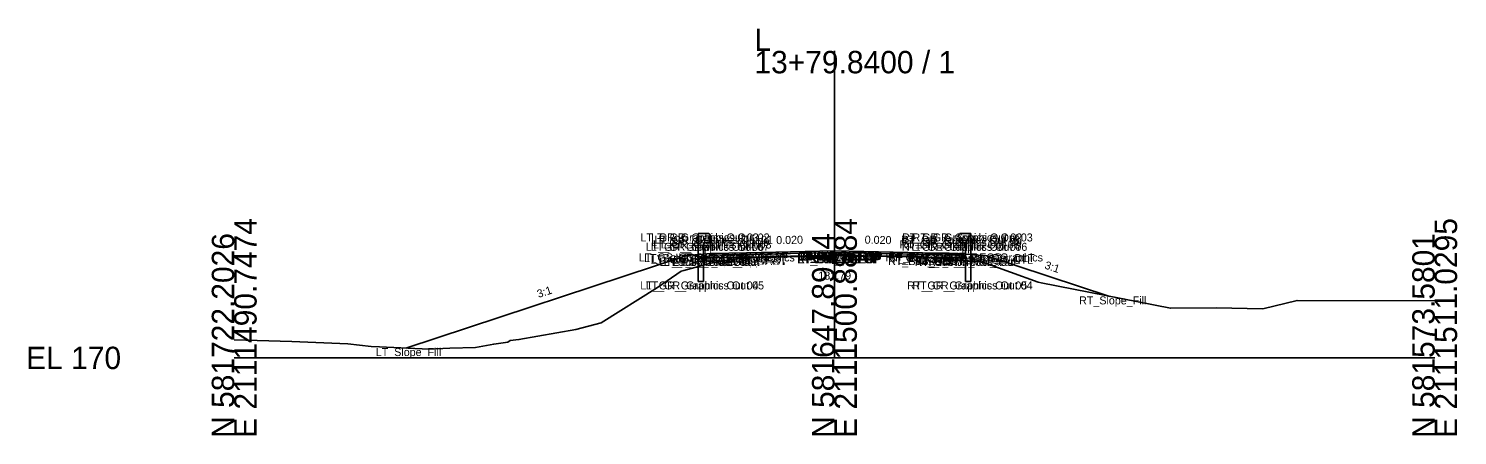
# Model space of a CAD drawing. Extents: x -26 to 3453, y -333 to 9539.
# Drawn here: x 3274.3 to 3452.8, y -9.7 to 41.2 of the extents above; entities that cross this region are included whole.
import ezdxf

# ---------------------------------------------------------------- set-up
doc = ezdxf.new("R2010")
doc.units = 0
for name, color, linetype in [('Default', 7, 'Continuous'), ('Exist Cross Section Cell', 7, 'Continuous'), ('Exist XS Ground Line', 7, 'Continuous'), ('Prop CMT Guardrail Graphics', 7, 'Continuous'), ('Prop CMT Pvmt Course 1', 7, 'Continuous'), ('Prop CMT Pvmt Course 2', 7, 'Continuous'), ('Prop CMT Pvmt Course 3', 7, 'Continuous'), ('Prop CMT Pvmt Surface', 7, 'Continuous'), ('Prop CMT Pvmt Surface Shoulder', 7, 'Continuous'), ('Prop CMT Shld Paved Course 1', 7, 'Continuous'), ('Prop CMT Shld Paved Course 2', 7, 'Continuous'), ('Prop CMT Shld Paved Course 3', 7, 'Continuous'), ('Prop CMT Slope Grass', 7, 'Continuous'), ('Prop CMT Subgrade Earthwork', 7, 'Continuous'), ('Prop XS SE Text', 7, 'Continuous'), ('Prop XS Side Slope Text', 7, 'Continuous'), ('Scratch_Level_0', 7, 'Continuous')]:
    doc.layers.add(name, color=color, linetype=linetype)

msp = doc.modelspace()

# ---------------------------------------------------------------- linework, layer by layer
at = {"layer": 'Exist Cross Section Cell'}
for p, q in [((3375, 0), (3375, 38.38)), ((3300, 0), (3375, 0)), ((3375, 0), (3450, 0))]:
    msp.add_line(p, q, dxfattribs=at)
at = {"layer": 'Exist XS Ground Line'}
msp.add_lwpolyline([(3300, 2.25), (3307.21, 2.07), (3314.19, 1.77), (3317.13, 1.43), (3318.14, 1.38), (3324.36, 1.1), (3326.96, 1.2), (3330.15, 1.32), (3332.44, 1.72), (3334.21, 1.97), (3334.5, 2.19), (3335.57, 2.3), (3342.68, 3.54), (3345.84, 4.38), (3352.91, 8.82), (3355.85, 10.84), (3356.18, 10.93), (3359.37, 11.8), (3361.97, 12.31), (3364.49, 12.5), (3372.37, 12.74), (3374.24, 12.79), (3375, 12.79), (3382.32, 12.74), (3384.22, 12.72), (3384.67, 12.7), (3385.36, 12.71), (3390.78, 12.17), (3393.52, 11.98), (3400.45, 9.48), (3400.84, 9.38), (3416.97, 6.2), (3422.69, 6.25), (3428.53, 6.15), (3432.8, 7.18), (3450, 7.13)], dxfattribs=at)
at = {"layer": 'Prop CMT Guardrail Graphics'}
for points in [[(3357.97, 9.56), (3357.97, 15.56)], [(3357.97, 15.56), (3359.3, 15.56), (3359.57, 15.27)], [(3359.57, 14.68), (3359.3, 14.39), (3358.64, 14.39)], [(3358.64, 14.39), (3358.64, 9.56)], [(3359.57, 15.27), (3359.3, 14.98)], [(3359.3, 14.98), (3359.57, 14.68)], [(3392.03, 15.56), (3390.7, 15.56), (3390.43, 15.27)], [(3390.43, 15.27), (3390.7, 14.98)], [(3390.7, 14.98), (3390.43, 14.68)], [(3390.43, 14.68), (3390.7, 14.39), (3391.36, 14.39)], [(3391.36, 14.39), (3391.36, 9.56)], [(3392.03, 9.56), (3392.03, 15.56)], [(3358.64, 9.56), (3357.97, 9.56)], [(3391.36, 9.56), (3392.03, 9.56)]]:
    msp.add_lwpolyline(points, dxfattribs=at)
at = {"layer": 'Prop CMT Pvmt Course 1'}
for points in [[(3375, 13.37), (3364, 13.15)], [(3364, 12.94), (3375, 13.16)], [(3364, 13.15), (3364, 12.94)], [(3375, 13.16), (3375, 13.37)], [(3375, 13.37), (3386, 13.15)], [(3375, 13.16), (3375, 13.37)], [(3386, 12.94), (3375, 13.16)], [(3386, 13.15), (3386, 12.94)]]:
    msp.add_lwpolyline(points, dxfattribs=at)
msp.add_lwpolyline([(3375, 13.16), (3375, 13.24), (3375, 13.24), (3375, 13.16)], close=True, dxfattribs=at)
msp.add_lwpolyline([(3375, 13.16), (3375, 13.24), (3375, 13.24), (3375, 13.16)], close=True, dxfattribs=at)
at = {"layer": 'Prop CMT Pvmt Course 2'}
for points in [[(3375, 13.16), (3364, 12.94)], [(3364, 12.94), (3364, 12.61)], [(3364, 12.61), (3375, 12.83)], [(3375, 12.83), (3375, 13.16)], [(3375, 12.83), (3375, 13.16)], [(3375, 13.16), (3386, 12.94)], [(3386, 12.61), (3375, 12.83)], [(3386, 12.94), (3386, 12.61)]]:
    msp.add_lwpolyline(points, dxfattribs=at)
at = {"layer": 'Prop CMT Pvmt Course 3'}
for points in [[(3375, 12.83), (3364, 12.61)], [(3364, 12.61), (3375, 12.83)], [(3364, 12.61), (3364, 12.61)], [(3375, 12.83), (3375, 12.83)], [(3375, 12.83), (3386, 12.61)], [(3386, 12.61), (3375, 12.83)], [(3375, 12.83), (3375, 12.83)], [(3386, 12.61), (3386, 12.61)]]:
    msp.add_lwpolyline(points, dxfattribs=at)
at = {"layer": 'Prop CMT Pvmt Surface'}
for points in [[(3375, 13.37), (3364, 13.15)], [(3375, 13.37), (3386, 13.15)]]:
    msp.add_lwpolyline(points, dxfattribs=at)
at = {"layer": 'Prop CMT Pvmt Surface Shoulder'}
for points in [[(3364, 13.15), (3359.58, 13.06)], [(3386, 13.15), (3390.42, 13.06)]]:
    msp.add_lwpolyline(points, dxfattribs=at)
at = {"layer": 'Prop CMT Shld Paved Course 1'}
for points in [[(3364, 13.15), (3359.58, 13.06), (3359.37, 12.85)], [(3359.37, 12.85), (3364, 12.94)], [(3364, 12.94), (3364, 13.15)], [(3386, 13.15), (3390.42, 13.06), (3390.63, 12.85)], [(3386, 12.94), (3386, 13.15)], [(3390.63, 12.85), (3386, 12.94)]]:
    msp.add_lwpolyline(points, dxfattribs=at)
at = {"layer": 'Prop CMT Shld Paved Course 2'}
for points in [[(3364, 12.94), (3359.37, 12.85), (3359.03, 12.51)], [(3359.03, 12.51), (3364, 12.61)], [(3364, 12.61), (3364, 12.94)], [(3386, 12.94), (3390.63, 12.85), (3390.97, 12.51)], [(3386, 12.61), (3386, 12.94)], [(3390.97, 12.51), (3386, 12.61)]]:
    msp.add_lwpolyline(points, dxfattribs=at)
at = {"layer": 'Prop CMT Shld Paved Course 3'}
for points in [[(3364, 12.61), (3359.03, 12.51)], [(3359.03, 12.51), (3364, 12.61)], [(3359.03, 12.51), (3359.03, 12.51), (3359.03, 12.51)], [(3364, 12.61), (3364, 12.61)], [(3386, 12.61), (3390.97, 12.51)], [(3390.97, 12.51), (3386, 12.61)], [(3386, 12.61), (3386, 12.61)], [(3390.97, 12.51), (3390.97, 12.51), (3390.97, 12.51)]]:
    msp.add_lwpolyline(points, dxfattribs=at)
at = {"layer": 'Prop CMT Slope Grass'}
for points in [[(3356.57, 12.82), (3321.46, 1.23)], [(3359.57, 13.06), (3356.57, 12.82)], [(3359.58, 13.06), (3359.57, 13.06)], [(3390.42, 13.06), (3390.43, 13.06)], [(3390.43, 13.06), (3394, 12.77)], [(3394, 12.77), (3409.39, 7.69)]]:
    msp.add_lwpolyline(points, dxfattribs=at)
at = {"layer": 'Prop CMT Subgrade Earthwork'}
for points in [[(3359.03, 12.51), (3358.56, 12.98)], [(3364, 12.61), (3359.03, 12.51)], [(3375, 12.83), (3364, 12.61)], [(3375, 12.83), (3386, 12.61)], [(3386, 12.61), (3390.97, 12.51)], [(3390.97, 12.51), (3391.44, 12.98)]]:
    msp.add_lwpolyline(points, dxfattribs=at)

# ---------------------------------------------------------------- texts
at = {"layer": 'Default'}
msp.add_text('-', height=0.0001, dxfattribs=at).set_placement((3300, 0))
at = {"layer": 'Exist Cross Section Cell'}
for s, p in [('L', (3365, 38.38)), ('13+79.8400 / 1', (3365, 35.58)), ('EL 170', (3274, -1.4))]:
    msp.add_text(s, height=2.8, dxfattribs=at).set_placement(p)
for s, p in [('E 2111490.7474', (3302.8, -10)), ('E 2111500.8884', (3377.8, -10)), ('E 2111511.0295', (3452.8, -10)), ('N 581722.2026', (3300, -10)), ('N 581647.8914', (3375, -10)), ('N 581573.5801', (3450, -10))]:
    msp.add_text(s, height=2.8, rotation=90, dxfattribs=at).set_placement(p)
at = {"layer": 'Exist XS Ground Line'}
msp.add_text('182.79', height=1, dxfattribs=at).set_placement((3372.99, 9.79))
at = {"layer": 'Prop XS SE Text'}
for rotation, p in [(1.1458, (3367.73, 14.22)), (358.8542, (3378.77, 14.29))]:
    msp.add_text('0.020', height=1, rotation=rotation, dxfattribs=at).set_placement(p)
at = {"layer": 'Prop XS Side Slope Text'}
for rotation, p in [(341.7371, (3401.18, 11.19)), (18.2629, (3338.03, 7.49))]:
    msp.add_text('3:1', height=1, rotation=rotation, dxfattribs=at).set_placement(p)
at = {"layer": 'Scratch_Level_0'}
for s, p in [('LT_GR_Graphics Out 03', (3350.75, 14.56)), ('LT_GR_Graphics Out 06', (3351.41, 13.39)), ('LT_GR_Graphics Out 07', (3352.06, 13.39)), ('LT_GR_Graphics Out 09', (3352.08, 13.98)), ('LT_GR_Graphics Out 02', (3352.1, 14.56)), ('LT_GR_Graphics Out 08', (3352.34, 13.68)), ('LT_GR_Graphics Out 01', (3352.52, 14.27)), ('RT_GR_Graphics Out 08', (3383.14, 13.68)), ('RT_GR_Graphics Out 01', (3383.31, 14.27)), ('RT_GR_Graphics Out 07', (3383.4, 13.39)), ('RT_GR_Graphics Out 09', (3383.41, 13.98)), ('RT_GR_Graphics Out 02', (3383.44, 14.56)), ('RT_GR_Graphics Out 06', (3384.08, 13.39)), ('RT_GR_Graphics Out 03', (3384.76, 14.56)), ('LT_GS_OS_GR_Face_Graphics', (3350.57, 12.06)), ('LT_Sub_Trench_Out_DLT', (3351.21, 11.98)), ('LT_GS_OS_CTL', (3352.04, 11.82)), ('LT_Sub_Trench_Out', (3353.14, 11.51)), ('LT_PS3_Shelf_Out', (3353.69, 11.51)), ('LT_PS3_OEOP', (3354.82, 11.51)), ('LT_PS2_OEOP', (3355.16, 11.85)), ('LT_PS1_OEOP', (3355.49, 12.06)), ('LT_PV2_OEOT', (3359.75, 11.94)), ('LT_PV3_OEOT', (3359.75, 11.61)), ('LT_Sub_OEOT', (3359.77, 11.61)), ('LT_PV1_OEOT', (3359.87, 12.15)), ('RT_PV2_OEEOP', (3370.33, 12.16)), ('RT_PV3_OEEOP', (3370.33, 11.83)), ('RT_Sub_OEEOP', (3370.36, 11.83)), ('LT_PV2_OEEOP', (3370.39, 12.16)), ('LT_PV3_OEEOP', (3370.39, 11.83)), ('LT_Sub_OEEOP', (3370.42, 11.83)), ('RT_PV1_OEEOP', (3370.45, 12.24)), ('LT_PV1_OEEOP', (3370.51, 12.24)), ('RT_PV2_IEEOP', (3370.71, 12.16)), ('LT_PV2_IEEOP', (3370.77, 12.16)), ('RT_PV1_IEEOP', (3370.83, 12.24)), ('LT_PV1_IEEOP', (3370.89, 12.24)), ('PV2_PGL', (3372.35, 12.16)), ('PV1_PGL', (3372.47, 12.37)), ('RT_GS_OS_GR_Face_Graphics', (3381.36, 12.06)), ('RT_PV2_OEOT', (3381.69, 11.94)), ('RT_PV3_OEOT', (3381.69, 11.61)), ('RT_Sub_OEOT', (3381.71, 11.61)), ('RT_PV1_OEOT', (3381.81, 12.15)), ('RT_Sub_Trench_Out_DLT', (3384.03, 11.98)), ('RT_Sub_Trench_Out', (3385.02, 11.51)), ('RT_PS3_Shelf_Out', (3385.57, 11.51)), ('RT_PS1_OEOP', (3386.26, 12.06)), ('RT_PS2_OEOP', (3386.36, 11.85)), ('RT_PS3_OEOP', (3386.7, 11.51)), ('RT_GS_OS_CTL', (3389.4, 11.77)), ('LT_GR_Graphics Out 04', (3350.74, 8.56)), ('LT_GR_Graphics Out 05', (3351.41, 8.56)), ('RT_GR_Graphics Out 05', (3384.08, 8.56)), ('RT_GR_Graphics Out 04', (3384.74, 8.56)), ('RT_Slope_Fill', (3405.57, 6.69)), ('LT_Slope_Fill', (3317.69, 0.23))]:
    msp.add_text(s, height=1, dxfattribs=at).set_placement(p)

doc.saveas('drawing.dxf')
